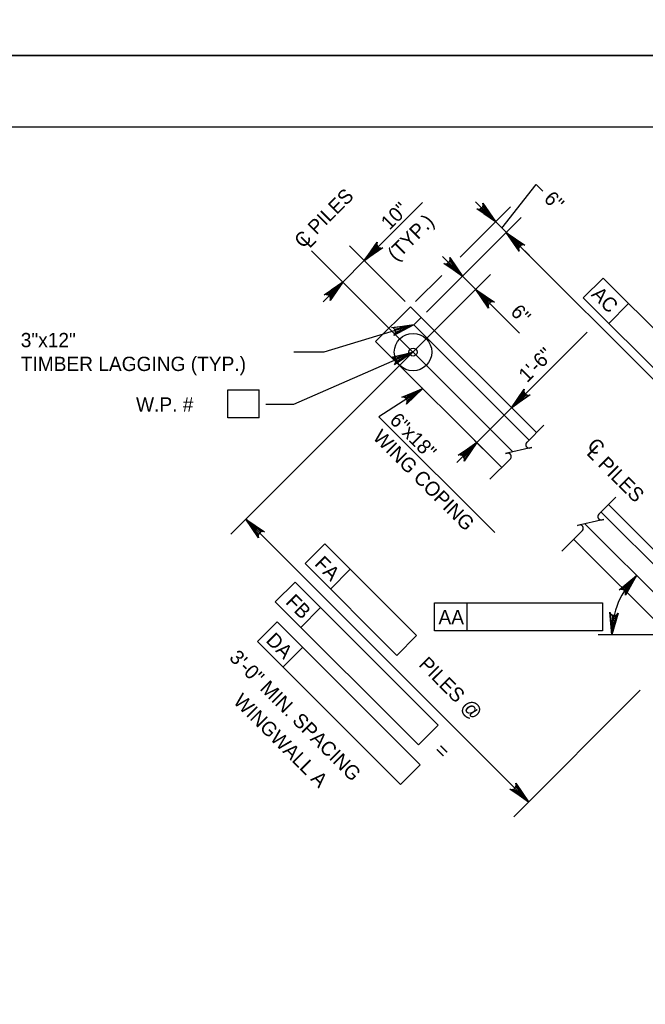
# Model space of a CAD drawing. Extents: x 638304 to 640306, y 296653 to 298435.
# Drawn here: x 638484.2 to 638615.5, y 297642.3 to 297849 of the extents above; entities that cross this region are included whole.
import ezdxf

# ---------------------------------------------------------------- set-up
doc = ezdxf.new("R2010")
doc.units = 0
for name, color, linetype in [('2', 7, 'Continuous'), ('Level 2', 7, 'Continuous'), ('Level 4', 7, 'Continuous'), ('Level 5', 7, 'Continuous'), ('Level 52', 7, 'Continuous'), ('PLT-BNDY', 7, 'Continuous')]:
    doc.layers.add(name, color=color, linetype=linetype)

msp = doc.modelspace()

# ---------------------------------------------------------------- linework, layer by layer
at = {"layer": '2'}
msp.add_line((638475.46, 297826.46), (639261.46, 297826.46), dxfattribs=at)
at = {"layer": 'Level 2'}
for p, q in [((638566.19, 297788.71), (638558.89, 297781.42)), ((638592.63, 297762.27), (638566.19, 297788.71)), ((638585.34, 297754.97), (638558.89, 297781.42)), ((638627.67, 297727.22), (638607.71, 297747.18)), ((638623.4, 297716.91), (638600.42, 297739.89))]:
    msp.add_line(p, q, dxfattribs=at)
at = {"layer": 'Level 4'}
for p, q in [((638568.45, 297786.46), (638566.88, 297784.89)), ((638591.07, 297760.7), (638566.88, 297784.89)), ((638631.84, 297719.94), (638606.15, 297745.62))]:
    msp.add_line(p, q, dxfattribs=at)
msp.add_circle((638566.73, 297779.18), 3.93, dxfattribs=at)
at = {"layer": 'Level 5'}
for p, q in [((638585.38, 297805.22), (638592.54, 297814.39)), ((638592.54, 297814.39), (638593.97, 297812.97)), ((638556.52, 297798.38), (638568.7, 297810.58)), ((638584.03, 297806.56), (638579.87, 297810.73)), ((638576.59, 297799.11), (638587.16, 297809.69)), ((638569.53, 297787.54), (638589.42, 297807.43)), ((638589.25, 297801.35), (638584.04, 297806.56)), ((638645.52, 297745.07), (638586.29, 297804.3)), ((638587.68, 297758.23), (638545.45, 297800.46)), ((638565.1, 297789.8), (638553.39, 297801.51)), ((638589.07, 297801.52), (638591.16, 297799.44)), ((638552.02, 297793.89), (638556.51, 297798.38)), ((638569.53, 297787.54), (638580.23, 297798.24)), ((638577.11, 297795.12), (638572.94, 297799.28)), ((638583.01, 297795.47), (638528.53, 297740.98)), ((638552.02, 297793.89), (638547.85, 297789.72)), ((638567.27, 297789.8), (638572.77, 297795.29)), ((638577.11, 297795.12), (638579.89, 297792.34)), ((638606.61, 297794.72), (638602.44, 297790.55)), ((638606.61, 297794.72), (638636.62, 297764.71)), ((638579.89, 297792.34), (638589.09, 297783.13)), ((638602.44, 297790.55), (638632.45, 297760.54)), ((638611.95, 297789.38), (638607.78, 297785.21)), ((638587.4, 297767.5), (638603.25, 297783.36)), ((638527.89, 297765.37), (638527.89, 297771.27)), ((638527.89, 297771.27), (638534.47, 297771.27)), ((638534.47, 297765.37), (638534.47, 297771.27)), ((638580.1, 297760.21), (638587.4, 297767.5)), ((638586.96, 297767.94), (638590.52, 297764.38)), ((638534.47, 297765.37), (638527.89, 297765.37)), ((638594.19, 297763.82), (638590.61, 297760.24)), ((638579.66, 297760.65), (638583.23, 297757.08)), ((638580.1, 297760.21), (638575.94, 297756.04)), ((638587.18, 297756.81), (638582.87, 297752.5)), ((638609.28, 297748.75), (638605.7, 297745.17)), ((638609.28, 297748.75), (638605.7, 297745.17)), ((638590.98, 297684.78), (638531.65, 297744.1)), ((638602.27, 297741.74), (638597.96, 297737.43)), ((638602.27, 297741.74), (638597.96, 297737.43)), ((638628.27, 297717.64), (638602.75, 297743.16)), ((638548.23, 297738.95), (638544.07, 297734.78)), ((638548.23, 297738.95), (638567.49, 297719.69)), ((638544.07, 297734.78), (638563.33, 297715.52)), ((638553.57, 297733.61), (638549.4, 297729.45)), ((638542.01, 297730.91), (638537.84, 297726.74)), ((638542.01, 297730.91), (638572.02, 297700.9)), ((638537.84, 297726.74), (638567.85, 297696.73)), ((638547.34, 297725.57), (638543.18, 297721.4)), ((638571.26, 297726.58), (638606.5, 297726.58)), ((638571.26, 297720.69), (638571.26, 297726.58)), ((638578.09, 297720.69), (638578.09, 297726.58)), ((638606.5, 297726.58), (638606.5, 297720.69)), ((638538.24, 297722.58), (638534.07, 297718.42)), ((638538.24, 297722.58), (638568.25, 297692.57)), ((638567.49, 297719.69), (638563.33, 297715.52)), ((638606.5, 297720.69), (638571.26, 297720.69)), ((638897.93, 297719.86), (638605.59, 297719.86)), ((638534.07, 297718.42), (638564.08, 297688.41)), ((638543.58, 297717.25), (638539.41, 297713.08)), ((638614.39, 297708.2), (638587.85, 297681.66)), ((638572.02, 297700.9), (638567.85, 297696.73)), ((638568.25, 297692.57), (638564.08, 297688.41))]:
    msp.add_line(p, q, dxfattribs=at)
for points in [[(638584.03, 297806.56), (638580.13, 297809.23), (638580.56, 297809.16), (638580.91, 297809.25), (638581.17, 297809.43), (638581.35, 297809.69), (638581.44, 297810.04), (638581.36, 297810.47), (638584.03, 297806.56), (638581.44, 297810.04), (638581.35, 297809.69), (638584.03, 297806.56), (638581.17, 297809.43), (638580.91, 297809.25), (638584.03, 297806.56), (638580.56, 297809.16)], [(638586.29, 297804.3), (638590.2, 297801.63), (638589.77, 297801.71), (638589.42, 297801.62), (638589.16, 297801.43), (638588.98, 297801.18), (638588.89, 297800.83), (638588.97, 297800.4), (638586.29, 297804.3), (638588.89, 297800.83), (638588.98, 297801.18), (638586.29, 297804.3), (638589.16, 297801.43), (638589.42, 297801.62), (638586.29, 297804.3), (638589.77, 297801.71)], [(638556.52, 297798.38), (638559.19, 297802.29), (638559.11, 297801.86), (638559.2, 297801.51), (638559.38, 297801.25), (638559.64, 297801.07), (638559.99, 297800.98), (638560.42, 297801.06), (638556.52, 297798.38), (638559.99, 297800.98), (638559.64, 297801.07), (638556.52, 297798.38), (638559.38, 297801.25), (638559.2, 297801.51), (638556.52, 297798.38), (638559.11, 297801.86)], [(638577.11, 297795.12), (638573.2, 297797.79), (638573.63, 297797.71), (638573.98, 297797.8), (638574.24, 297797.99), (638574.42, 297798.24), (638574.51, 297798.59), (638574.44, 297799.02), (638577.11, 297795.12), (638574.51, 297798.59), (638574.42, 297798.24), (638577.11, 297795.12), (638574.24, 297797.99), (638573.98, 297797.8), (638577.11, 297795.12), (638573.63, 297797.71)], [(638552.02, 297793.89), (638549.35, 297789.98), (638549.43, 297790.41), (638549.33, 297790.76), (638549.15, 297791.02), (638548.89, 297791.2), (638548.54, 297791.29), (638548.11, 297791.21), (638552.02, 297793.89), (638548.54, 297791.29), (638548.89, 297791.2), (638552.02, 297793.89), (638549.15, 297791.02), (638549.33, 297790.76), (638552.02, 297793.89), (638549.43, 297790.41)], [(638579.89, 297792.34), (638583.79, 297789.67), (638583.36, 297789.74), (638583.01, 297789.65), (638582.75, 297789.47), (638582.57, 297789.21), (638582.48, 297788.86), (638582.56, 297788.43), (638579.89, 297792.34), (638582.48, 297788.86), (638582.57, 297789.21), (638579.89, 297792.34), (638582.75, 297789.47), (638583.01, 297789.65), (638579.89, 297792.34), (638583.36, 297789.74)], [(638566.88, 297784.89), (638548.04, 297779.14), (638541.71, 297779.14)], [(638566.88, 297784.89), (638562.69, 297782.7), (638562.96, 297783.04), (638563.04, 297783.39), (638563, 297783.71), (638562.86, 297783.99), (638562.59, 297784.24), (638562.18, 297784.37), (638566.88, 297784.89), (638562.59, 297784.24), (638562.86, 297783.99), (638566.88, 297784.89), (638563, 297783.71), (638563.04, 297783.39), (638566.88, 297784.89), (638562.96, 297783.04)], [(638566.73, 297779.18), (638541.65, 297768.16), (638535.86, 297768.16)], [(638568.79, 297771.52), (638559.56, 297765.58), (638583.88, 297741.31)], [(638587.4, 297767.5), (638590.07, 297771.41), (638589.99, 297770.98), (638590.08, 297770.63), (638590.26, 297770.37), (638590.52, 297770.19), (638590.87, 297770.1), (638591.3, 297770.18), (638587.4, 297767.5), (638590.87, 297770.1), (638590.52, 297770.19), (638587.4, 297767.5), (638590.26, 297770.37), (638590.08, 297770.63), (638587.4, 297767.5), (638589.99, 297770.98)], [(638580.1, 297760.21), (638577.43, 297756.3), (638577.51, 297756.73), (638577.42, 297757.08), (638577.23, 297757.34), (638576.98, 297757.53), (638576.63, 297757.61), (638576.2, 297757.54), (638580.1, 297760.21), (638576.63, 297757.61), (638576.98, 297757.53), (638580.1, 297760.21), (638577.23, 297757.34), (638577.42, 297757.08), (638580.1, 297760.21), (638577.51, 297756.73)], [(638591.29, 297759.06), (638591.64, 297759.14), (638586.11, 297757.87), (638586.48, 297757.96)], [(638531.65, 297744.1), (638535.56, 297741.43), (638535.13, 297741.51), (638534.78, 297741.42), (638534.52, 297741.24), (638534.34, 297740.98), (638534.25, 297740.63), (638534.32, 297740.2), (638531.65, 297744.1), (638534.25, 297740.63), (638534.34, 297740.98), (638531.65, 297744.1), (638534.52, 297741.24), (638534.78, 297741.42), (638531.65, 297744.1), (638535.13, 297741.51)], [(638606.38, 297743.98), (638606.73, 297744.06), (638601.2, 297742.8), (638601.57, 297742.89)], [(638606.38, 297743.98), (638606.73, 297744.06), (638601.2, 297742.8), (638601.57, 297742.89)], [(638613.62, 297732.28), (638611.29, 297728.17), (638611.33, 297728.6), (638611.21, 297728.94), (638611.01, 297729.19), (638610.74, 297729.35), (638610.38, 297729.41), (638609.96, 297729.29), (638613.62, 297732.28), (638610.38, 297729.41), (638610.74, 297729.35), (638613.62, 297732.28), (638611.01, 297729.19), (638611.21, 297728.94), (638613.62, 297732.28), (638611.33, 297728.6)], [(638608.44, 297719.85), (638608.04, 297724.57), (638608.26, 297724.18), (638608.55, 297723.97), (638608.85, 297723.88), (638609.17, 297723.91), (638609.5, 297724.06), (638609.78, 297724.39), (638608.44, 297719.85), (638609.5, 297724.06), (638609.17, 297723.91), (638608.44, 297719.85), (638608.85, 297723.88), (638608.55, 297723.97), (638608.44, 297719.85), (638608.26, 297724.18)], [(638590.98, 297684.78), (638587.07, 297687.45), (638587.5, 297687.38), (638587.85, 297687.47), (638588.11, 297687.65), (638588.29, 297687.91), (638588.38, 297688.26), (638588.3, 297688.69), (638590.98, 297684.78), (638588.38, 297688.26), (638588.29, 297687.91), (638590.98, 297684.78), (638588.11, 297687.65), (638587.85, 297687.47), (638590.98, 297684.78), (638587.5, 297687.38)]]:
    msp.add_lwpolyline(points, dxfattribs=at)
for points in [[(638582.3, 297808.99), (638581.61, 297808.3), (638584.04, 297806.56)], [(638588.73, 297802.57), (638588.03, 297801.87), (638586.29, 297804.3)], [(638558.25, 297800.82), (638558.95, 297800.12), (638556.51, 297798.38)], [(638575.37, 297797.55), (638574.68, 297796.85), (638577.11, 297795.12)], [(638549.59, 297792.15), (638550.28, 297791.46), (638552.02, 297793.89)], [(638582.32, 297790.6), (638581.62, 297789.91), (638579.89, 297792.34)], [(638566.88, 297784.89), (638563.99, 297784.27), (638564.13, 297783.8)], [(638589.13, 297769.93), (638589.83, 297769.24), (638587.4, 297767.5)], [(638577.67, 297758.47), (638578.37, 297757.78), (638580.1, 297760.21)], [(638534.08, 297742.37), (638533.39, 297741.67), (638531.65, 297744.1)], [(638589.24, 297687.21), (638588.54, 297686.52), (638590.98, 297684.78)]]:
    msp.add_lwpolyline(points, close=True, dxfattribs=at)
msp.add_circle((638566.73, 297779.18), 0.849, dxfattribs=at)
for centre, radius, start, end in [((638591.11, 297759.74), 0.709, 135, 285), ((638586.64, 297757.27), 0.709, 320.3286, 102.8672), ((638606.2, 297744.67), 0.709, 135, 285), ((638606.2, 297744.67), 0.709, 135, 285), ((638601.73, 297742.19), 0.709, 320.3286, 102.8672), ((638601.73, 297742.19), 0.709, 320.3286, 102.8672), ((638625.92, 297719.86), 17.48, 134.7007, 179.9991)]:
    msp.add_arc(centre, radius, start, end, dxfattribs=at)
at = {"layer": 'Level 52'}
for points in [[(638566.73, 297779.18), (638562.82, 297776.51), (638563.05, 297776.88), (638563.09, 297777.24), (638563.02, 297777.55), (638562.84, 297777.81), (638562.55, 297778.02), (638562.12, 297778.11), (638566.73, 297779.18), (638562.55, 297778.02), (638562.84, 297777.81), (638566.73, 297779.18), (638563.02, 297777.55), (638563.09, 297777.24), (638566.73, 297779.18), (638563.05, 297776.88)], [(638568.79, 297771.52), (638565.35, 297768.27), (638565.52, 297768.67), (638565.51, 297769.03), (638565.38, 297769.33), (638565.17, 297769.56), (638564.85, 297769.72), (638564.41, 297769.74), (638568.79, 297771.52), (638564.85, 297769.72), (638565.17, 297769.56), (638568.79, 297771.52), (638565.38, 297769.33), (638565.51, 297769.03), (638568.79, 297771.52), (638565.52, 297768.67)]]:
    msp.add_lwpolyline(points, dxfattribs=at)
at = {"layer": 'PLT-BNDY'}
for points in [[(638435.46, 298435.46), (639276.46, 298435.46), (639276.46, 297841.46), (638435.46, 297841.46)], [(638435.46, 297841.46), (639276.46, 297841.46), (639276.46, 297247.46), (638435.46, 297247.46)]]:
    msp.add_lwpolyline(points, close=True, dxfattribs=at)

# ---------------------------------------------------------------- texts
at = {"layer": 'Level 5'}
for s, height, rotation, p in [('C PILES', 3, 45, (638543.63, 297800.81)), ('6"', 3, 315, (638593.99, 297811.15)), ('10"', 3, 45, (638561.8, 297804.65)), ('(TYP.)', 3, 45, (638563.19, 297798.1)), ('L', 3, 45, (638545.02, 297800.83)), ('AC', 3, 314.9382, (638603.95, 297791.1)), ('6"', 3, 315, (638587, 297787.4)), ('1\'-6"', 3, 45, (638590.67, 297772.64)), ('6"x18"', 3, 315, (638561.63, 297764.64)), ('WING COPING', 3.0001, 315, (638558.1, 297761.11)), ('C', 3, 315, (638603.07, 297759.36)), ('L PILES', 3, 315, (638602.98, 297757.81)), ('FA', 3, 314.9382, (638545.89, 297734.56)), ('FB', 3, 314.9382, (638539.83, 297726.54)), ('DA', 3, 314.9382, (638535.69, 297718.47)), ('3\'-0" MIN. SPACING', 3.0001, 315, (638528, 297714.84)), ('PILES @', 3, 314.9382, (638567.73, 297713.41)), ('WINGWALL A', 3, 315, (638528.86, 297705.68)), ('=', 3, 314.9382, (638570.97, 297695.3))]:
    msp.add_text(s, height=height, rotation=rotation, dxfattribs=at).set_placement(p)
for s, height, p in [('3"x12"', 3, (638484.44, 297780.21)), ('TIMBER LAGGING (TYP.)', 3.0001, (638484.44, 297775.21)), ('W.P. # ', 3, (638508.62, 297766.69)), ('AA', 3, (638572.07, 297722.04))]:
    msp.add_text(s, height=height, dxfattribs=at).set_placement(p)

doc.saveas('drawing.dxf')
